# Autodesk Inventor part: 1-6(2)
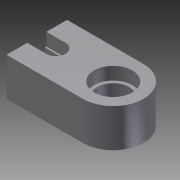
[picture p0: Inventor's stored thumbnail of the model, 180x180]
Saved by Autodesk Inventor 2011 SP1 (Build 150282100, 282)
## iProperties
Created: 2014-02
Part Number: 1-6(2)
Document SubType Name: Modeling
Designer: Administrator
Density: 1 g/cm^3
Author: Administrator
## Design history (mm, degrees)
sketch "草图1"
  geometry: L1 (-12, 9.5)-(12, 9.5); L2 (12, -9.5)-(-12, -9.5); L3 (-12, -9.5)-(-12, 9.5); A1 r 9.5 centre (12, 0) between (12, -9.5) and (12, 9.5); 3 further points
  constraints: 6 end point, 2 point on circle, 1 centre point, 1 coincident, 1 horizontal, 1 horizontal alignment, 1 midpoint, 1 parallel, 1 vertical alignment
extrude "拉伸1" new body sketch "草图1" distance "d0" = 12; taper "d1" = 0 deg
sketch "草图2"
  geometry: L1 (-12, -9.5)-(-12, 9.5) reference; L2 (-6, -2.5)-(-12, -2.5); L3 (-6, 2.5)-(-12, 2.5); A1 r 2.5 centre (-6, 0) between (-6, -2.5) and (-6, 2.5); 1 further point
  constraints: 4 end point, 2 perpendicular, 2 point on circle, 2 point on line, 2 tangent, 1 centre point
  dimensions: "d3" = 5 diameter of A1
extrude "拉伸2" cut sketch "草图2" stored distance "d4" = 16; taper "d5" = 0 deg
sketch "草图3"
  geometry: L1 (-6, -2.5)-(-12, -2.5) reference; L2 (-12, -9.5)-(-12, -2.5) reference; L3 (-12, 2.5)-(-12, 9.5) reference; L4 (-12, 2.5)-(-6, 2.5) reference; L5 (-6, 3)-(-12, 3); L6 (-6, -3)-(-12, -3); L7 (-12, 3)-(-12, -3); A1 r 2.5 centre (-6, 0) between (-6, -2.5) and (-6, 2.5) reference; A2 r 3 centre (-6, 0) between (-6, -3) and (-6, 3); 1 further point
  constraints: 6 end point, 3 perpendicular, 2 point on circle, 2 point on line, 2 tangent, 1 centre point, 1 coincident
  dimensions: "d6" = 6 diameter of A2
extrude "拉伸3" cut sketch "草图3" distance "d7" = 4; taper "d8" = 0 deg
hole "Hole1" diameter "d11" = 10; stored, may be unused: countersink angle "d15" = 90 deg, drill point angle "d17" = 118 deg; dims "d9" = 10, "d10" = 10, "d12" = 6, "d13" = 4, "d14" = 2, "d16" = 8
sketch "草图4"
  geometry: C1 r 5 at (12, 0) reference; C2 r 6 at (12, 0); A1 r 9.5 centre (12, 0) between (12, -9.5) and (12, 9.5) reference; 1 further point
  constraints: 1 centre point, 1 coincident
  dimensions: "d18" = 12 diameter of C2
extrude "拉伸4" cut sketch "草图4" distance "d19" = 4; taper "d20" = 0 deg
node "实体1"
